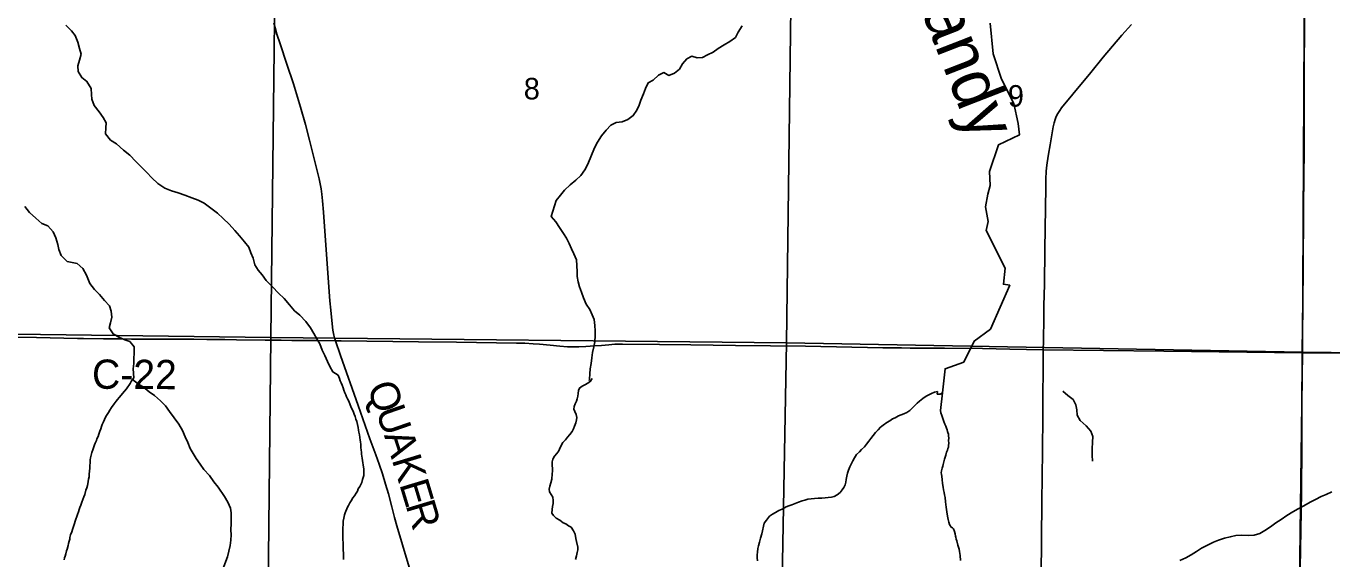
# Model space of a CAD drawing. Extents: x 0 to 34, y 0 to 22.
# Drawn here: x 3.988 to 6.524, y 15.838 to 16.874 of the extents above; entities that cross this region are included whole.
import ezdxf

# ---------------------------------------------------------------- set-up
doc = ezdxf.new("R2010")
doc.units = 0
for name, color, linetype in [('GM_X_Corporation', 7, 'Continuous'), ('GM_X_County_Road', 7, 'Continuous'), ('GM_X_County_Road_Text', 7, 'Continuous'), ('GM_X_Minor_River', 7, 'Continuous'), ('GM_X_Minor_River_Text', 7, 'Continuous'), ('GM_X_Section_Text', 7, 'Continuous'), ('GM_X_State_Route', 7, 'Continuous'), ('GM_X_Township_Road', 7, 'Continuous')]:
    doc.layers.add(name, color=color, linetype=linetype)

msp = doc.modelspace()

# ---------------------------------------------------------------- linework, layer by layer
at = {"layer": 'GM_X_Corporation'}
for points in [[(4.475, 17.2762), (4.463, 16.2688), (3.4681, 16.2816), (3.4847, 17.2912)], [(5.4781, 17.2612), (5.4651, 16.258), (4.463, 16.2688), (4.475, 17.2762)], [(6.4721, 17.2442), (6.4674, 16.2404), (5.4651, 16.258), (5.4781, 17.2612)], [(7.4742, 17.2327), (7.4675, 16.2282), (6.4674, 16.2404), (6.4721, 17.2442)], [(3.4681, 16.2816), (4.463, 16.2688), (4.4514, 15.172), (3.4532, 15.1884), (3.4534, 15.28)], [(4.463, 16.2688), (5.4651, 16.258), (5.4447, 15.1591), (4.4514, 15.172)], [(5.4651, 16.258), (6.4674, 16.2404), (6.4527, 15.1394), (5.4447, 15.1591)], [(6.4674, 16.2404), (7.4675, 16.2282), (7.4535, 15.1233), (6.4527, 15.1394)]]:
    msp.add_lwpolyline(points, close=True, dxfattribs=at)
at = {"layer": 'GM_X_County_Road'}
for points in [[(4.5885, 16.2621), (4.5867, 16.2677), (4.5855, 16.2731), (4.5838, 16.2828), (4.5822, 16.2951), (4.5795, 16.3217), (4.578, 16.3396), (4.5714, 16.4301), (4.5656, 16.5119), (4.5637, 16.5342), (4.5623, 16.5472), (4.5607, 16.5577), (4.559, 16.5669), (4.5569, 16.5767), (4.5382, 16.6521), (4.5303, 16.6825), (4.5205, 16.7162), (4.5073, 16.7613), (4.4945, 16.7999), (4.4811, 16.8393), (4.4749, 16.8582), (4.4714, 16.8701), (4.469, 16.8803)], [(3.9668, 16.2691), (4.0078, 16.2685), (4.0873, 16.2667), (4.0992, 16.2666), (4.1383, 16.266), (4.1705, 16.2658), (4.1923, 16.2655), (4.219, 16.2653), (4.2655, 16.2653), (4.2804, 16.2652), (4.3134, 16.2651), (4.3388, 16.2649), (4.3612, 16.2648), (4.3736, 16.2647), (4.3966, 16.2644), (4.4519, 16.2637), (4.4619, 16.2637), (4.483, 16.2634), (4.5041, 16.2631), (4.532, 16.2628), (4.5542, 16.2626), (4.5885, 16.2621), (4.6, 16.262), (4.7497, 16.2602), (4.8237, 16.2594), (4.9404, 16.2579), (4.9566, 16.2574), (4.9727, 16.2566), (4.985, 16.2555), (5.006, 16.2534), (5.0246, 16.2516), (5.0395, 16.2507), (5.0519, 16.2503), (5.0613, 16.2504), (5.075, 16.2509), (5.0917, 16.2521), (5.1053, 16.2533), (5.1195, 16.2546), (5.1312, 16.2555), (5.1387, 16.2558), (5.1461, 16.2559), (5.2181, 16.2549), (5.279, 16.2542), (5.366, 16.2531), (5.502, 16.2515), (5.6517, 16.2488), (5.6883, 16.2484), (5.7051, 16.2482), (5.7715, 16.2476), (5.8459, 16.2471), (5.8986, 16.2457), (5.9637, 16.2448)], [(4.7453, 15.7773), (4.7186, 15.8659), (4.7078, 15.9029), (4.7035, 15.9191), (4.6983, 15.9396), (4.6915, 15.9648), (4.686, 15.9839), (4.6799, 16.0035), (4.6735, 16.0223), (4.667, 16.0405), (4.6557, 16.0714), (4.6326, 16.1364), (4.5985, 16.2337), (4.5885, 16.2621)], [(5.9637, 16.2448), (6.198, 16.2422), (6.4665, 16.239), (6.7005, 16.2366), (6.9049, 16.2341), (7.1297, 16.2306), (7.2895, 16.2286), (7.3138, 16.2288)]]:
    msp.add_lwpolyline(points, dxfattribs=at)
at = {"layer": 'GM_X_Minor_River'}
for points in [[(4.065, 16.8753), (4.0758, 16.8648), (4.0829, 16.8552), (4.0879, 16.8422), (4.0915, 16.8304), (4.0944, 16.8194), (4.0915, 16.8073), (4.0879, 16.7964), (4.0888, 16.7857), (4.0958, 16.7738), (4.1059, 16.7661), (4.114, 16.7526), (4.1145, 16.7409), (4.1151, 16.7314), (4.1202, 16.7192), (4.1298, 16.7069), (4.1376, 16.6961), (4.1431, 16.6858), (4.1426, 16.6759), (4.142, 16.6642), (4.152, 16.6518), (4.1632, 16.6448), (4.1767, 16.6328), (4.1894, 16.6231), (4.2009, 16.6104), (4.2121, 16.5995), (4.2225, 16.5891), (4.2322, 16.5791), (4.2438, 16.5679), (4.2569, 16.5589), (4.2701, 16.5537), (4.2833, 16.5497), (4.2961, 16.5453), (4.3097, 16.5401), (4.3221, 16.5353), (4.3338, 16.5294), (4.3469, 16.5201), (4.3596, 16.51), (4.3708, 16.4999), (4.3823, 16.4887), (4.3931, 16.4764), (4.402, 16.4664), (4.4121, 16.4548), (4.4202, 16.4444), (4.4246, 16.4333), (4.4286, 16.423), (4.4321, 16.4101), (4.4384, 16.3997), (4.4462, 16.3901), (4.4543, 16.3793), (4.4662, 16.3673), (4.4781, 16.3546), (4.4889, 16.3442), (4.4994, 16.3322), (4.5094, 16.3207), (4.5195, 16.3117), (4.531, 16.2994), (4.5403, 16.2871), (4.5469, 16.2764), (4.5528, 16.266), (4.5583, 16.256), (4.563, 16.2442), (4.5681, 16.2335), (4.5732, 16.222), (4.578, 16.2121), (4.5835, 16.2017), (4.5942, 16.1957)], [(5.379, 16.8739), (5.3708, 16.8616), (5.3657, 16.8514), (5.3549, 16.8437), (5.3438, 16.8374), (5.3323, 16.8301), (5.3223, 16.8231), (5.3116, 16.8176), (5.3016, 16.8124), (5.2914, 16.8123), (5.2812, 16.8151), (5.2712, 16.81), (5.2627, 16.8003), (5.2568, 16.7901), (5.2472, 16.782), (5.2361, 16.778), (5.2263, 16.7835), (5.2164, 16.7784), (5.2056, 16.7684), (5.196, 16.7636), (5.1912, 16.7527), (5.1869, 16.7418), (5.1821, 16.7297), (5.1785, 16.7199), (5.1741, 16.7102), (5.1671, 16.6997), (5.1567, 16.6919), (5.1453, 16.6876), (5.1339, 16.6863), (5.1235, 16.6812), (5.1146, 16.6715), (5.1057, 16.6606), (5.0975, 16.6483), (5.092, 16.637), (5.0789, 16.6054), (5.0733, 16.5941), (5.0656, 16.5833), (5.0555, 16.5744), (5.0444, 16.5651), (5.0335, 16.5547), (5.0258, 16.545), (5.0172, 16.5349), (5.014, 16.5247), (5.0108, 16.5138), (5.0076, 16.5036), (5.0168, 16.4932), (5.0242, 16.4824), (5.0316, 16.4709), (5.0375, 16.4613), (5.0426, 16.451), (5.047, 16.4407), (5.0518, 16.4311), (5.0569, 16.4196), (5.0578, 16.4083), (5.0583, 16.3965), (5.0585, 16.387), (5.0602, 16.3767), (5.0627, 16.3668), (5.0663, 16.3565), (5.0707, 16.3455), (5.0758, 16.3332), (5.0828, 16.3229), (5.0875, 16.3129), (5.0911, 16.3034), (5.0928, 16.292), (5.093, 16.2817), (5.0932, 16.2722), (5.0926, 16.2605), (5.0906, 16.2507), (5.0881, 16.2393), (5.0867, 16.2291), (5.0854, 16.2182), (5.0837, 16.2079), (5.0831, 16.1977), (5.0822, 16.1879), (5.0818, 16.1849)], [(5.7677, 16.1608), (5.773, 16.208), (5.8091, 16.2204), (5.8295, 16.2615), (5.8614, 16.2851), (5.8985, 16.3701), (5.8861, 16.3721), (5.8898, 16.4036), (5.853, 16.4765), (5.8566, 16.4942), (5.8512, 16.5222), (5.8562, 16.5471), (5.8606, 16.5637), (5.8589, 16.5912), (5.8766, 16.6427), (5.9175, 16.6625), (5.9149, 16.6847), (5.9067, 16.7234), (5.8826, 16.7707), (5.8662, 16.8197), (5.8603, 16.8793)], [(3.9853, 16.5234), (3.9942, 16.5114), (4.0065, 16.5002), (4.0181, 16.4901), (4.0298, 16.4854), (4.0402, 16.4742), (4.0453, 16.4623), (4.0492, 16.4494), (4.0513, 16.4395), (4.056, 16.428), (4.0672, 16.4164), (4.077, 16.4144), (4.0872, 16.4123), (4.0977, 16.4026), (4.105, 16.3896), (4.1116, 16.3735), (4.1208, 16.3616), (4.1305, 16.352), (4.1402, 16.3404)], [(4.1402, 16.3404), (4.1495, 16.3304), (4.1527, 16.3201), (4.154, 16.3083), (4.1519, 16.2973), (4.1494, 16.2871), (4.1568, 16.2756), (4.1681, 16.269), (4.1794, 16.2642), (4.1892, 16.261), (4.1977, 16.2502), (4.1975, 16.2381), (4.1969, 16.2279), (4.1967, 16.218), (4.1958, 16.2078)], [(4.1101, 15.9981), (4.1105, 16.0015), (4.1108, 16.0099), (4.1113, 16.0137), (4.1114, 16.0197), (4.112, 16.0254), (4.1121, 16.0307), (4.113, 16.0349), (4.1143, 16.0402), (4.1156, 16.0451), (4.1176, 16.0503), (4.1189, 16.0545), (4.1209, 16.0598), (4.1222, 16.0631), (4.1242, 16.0684), (4.1254, 16.0718), (4.1275, 16.0763), (4.1287, 16.0808), (4.1308, 16.0865), (4.1328, 16.0913), (4.1341, 16.0959), (4.1357, 16.0996), (4.1378, 16.1049), (4.1402, 16.1094), (4.1426, 16.1154), (4.1454, 16.1187), (4.1478, 16.1232), (4.1506, 16.1277), (4.1533, 16.1326), (4.1589, 16.14), (4.1624, 16.1448), (4.1652, 16.1482), (4.1683, 16.1519), (4.1722, 16.1563), (4.175, 16.1601), (4.1789, 16.1645), (4.1825, 16.169), (4.1896, 16.179), (4.192, 16.1828), (4.1944, 16.1869), (4.1967, 16.1902), (4.1958, 16.2078)], [(4.1944, 16.1869), (4.2061, 16.1781), (4.2158, 16.1722), (4.2266, 16.1631), (4.237, 16.1556), (4.2488, 16.1458), (4.2588, 16.136), (4.2665, 16.1251), (4.2756, 16.1127), (4.2844, 16.1003), (4.2916, 16.088), (4.297, 16.0757), (4.3016, 16.0649), (4.3066, 16.053), (4.312, 16.043), (4.3182, 16.0333), (4.3258, 16.0224), (4.3328, 16.012), (4.3438, 16.0007), (4.3522, 15.9883), (4.3606, 15.9778), (4.3734, 15.9596), (4.3799, 15.9488), (4.3849, 15.9372), (4.3858, 15.9277), (4.3863, 15.917), (4.3864, 15.9072), (4.3857, 15.895), (4.3861, 15.8851), (4.3855, 15.8749), (4.384, 15.8643), (4.3818, 15.8534), (4.3789, 15.8424), (4.3699, 15.8184)], [(4.5942, 16.1957), (4.5962, 16.1888)], [(4.5962, 16.1888), (4.5976, 16.1846), (4.5998, 16.1804), (4.6019, 16.1761), (4.6037, 16.1711), (4.6051, 16.1665), (4.6072, 16.1612), (4.609, 16.1573), (4.6104, 16.1535), (4.6122, 16.1492), (4.6147, 16.1446), (4.6172, 16.1381), (4.62, 16.1312), (4.6229, 16.1254), (4.625, 16.1196), (4.6268, 16.115), (4.6285, 16.11), (4.6299, 16.1054), (4.6313, 16.0993), (4.6326, 16.0936), (4.6336, 16.0886), (4.6342, 16.0844), (4.6352, 16.0794), (4.6359, 16.0741), (4.6369, 16.0691), (4.6371, 16.0657), (4.6377, 16.0604), (4.638, 16.055), (4.6386, 16.0497), (4.6392, 16.0459), (4.6395, 16.0417), (4.6398, 16.0383), (4.6404, 16.0344), (4.641, 16.0295), (4.6417, 16.0253), (4.6427, 16.0211), (4.6433, 16.0169), (4.644, 16.0131), (4.6436, 16.0005), (4.6428, 15.9968), (4.6411, 15.993), (4.6398, 15.987), (4.6378, 15.9832), (4.6362, 15.9791), (4.633, 15.9746), (4.6314, 15.9701), (4.629, 15.966), (4.6254, 15.9608), (4.6227, 15.957), (4.6191, 15.9514), (4.6163, 15.9473), (4.6139, 15.9425), (4.6123, 15.9391), (4.6074, 15.9278), (4.6062, 15.9241), (4.6049, 15.9177), (4.6039, 15.9116), (4.6037, 15.9055), (4.6032, 15.8991), (4.603, 15.8938), (4.6029, 15.89), (4.6028, 15.8854), (4.603, 15.8793), (4.6033, 15.8755), (4.6035, 15.8706), (4.6037, 15.8652), (4.6035, 15.8561), (4.604, 15.8489), (4.6042, 15.8428), (4.6045, 15.8371)], [(5.0876, 16.189), (5.0841, 16.1837), (5.079, 16.1797), (5.0732, 16.1768), (5.0679, 16.1743), (5.0628, 16.1703), (5.0608, 16.1654), (5.0599, 16.1601), (5.0593, 16.1548), (5.0584, 16.1495), (5.0568, 16.1446), (5.054, 16.1398), (5.0523, 16.1345), (5.0518, 16.1296), (5.0535, 16.1246), (5.056, 16.1188), (5.0574, 16.1134), (5.0569, 16.1085), (5.0556, 16.1029), (5.0531, 16.0965), (5.0511, 16.0912), (5.0487, 16.086), (5.0439, 16.0804), (5.0396, 16.0752), (5.0353, 16.0696), (5.0302, 16.0644), (5.0254, 16.0547), (5.0229, 16.0483), (5.019, 16.0431), (5.0143, 16.0383), (5.0107, 16.0323), (5.0094, 16.027), (5.0096, 16.0202), (5.0106, 16.0141), (5.01, 16.0088), (5.0099, 16.0038), (5.0088, 15.9932), (5.0071, 15.9861), (5.005, 15.98), (5.0037, 15.974), (5.0044, 15.969), (5.0076, 15.9636), (5.0109, 15.9586), (5.0115, 15.9517), (5.0113, 15.946), (5.0104, 15.94), (5.0095, 15.9347), (5.0092, 15.9275), (5.0121, 15.9225), (5.0177, 15.9174), (5.0244, 15.9134), (5.0307, 15.9086), (5.036, 15.9066), (5.0412, 15.9026), (5.0464, 15.8998), (5.0511, 15.8929), (5.054, 15.8863), (5.0553, 15.8783), (5.057, 15.8722), (5.0597, 15.8614), (5.0592, 15.8561), (5.0583, 15.8508), (5.057, 15.8444), (5.0549, 15.8373)], [(5.7524, 16.1622), (5.7463, 16.1597), (5.7413, 16.1572), (5.7359, 16.1543), (5.7297, 16.1503), (5.7235, 16.1451), (5.7184, 16.1411), (5.7044, 16.1267), (5.6985, 16.1226), (5.6928, 16.1205), (5.6878, 16.1184), (5.6824, 16.1163), (5.6759, 16.1127), (5.6709, 16.1105), (5.6658, 16.1069), (5.6597, 16.1032), (5.6527, 16.0985), (5.6477, 16.0944), (5.6426, 16.0893), (5.6375, 16.0837), (5.6332, 16.0785), (5.6288, 16.0726), (5.6249, 16.067), (5.6202, 16.0614), (5.6162, 16.0562), (5.6108, 16.051), (5.6065, 16.0462), (5.601, 16.0411), (5.597, 16.0351), (5.5938, 16.0291), (5.5906, 16.0227), (5.5878, 16.0171), (5.5853, 16.0111), (5.5833, 16.0051), (5.582, 15.9994), (5.5807, 15.993), (5.5801, 15.9877), (5.5788, 15.9824), (5.576, 15.9772), (5.5732, 15.9723), (5.5689, 15.9675), (5.5635, 15.9631), (5.5577, 15.9598), (5.5524, 15.9584), (5.5455, 15.9575), (5.5398, 15.9569), (5.5333, 15.9567), (5.5261, 15.9565), (5.5193, 15.9556), (5.5128, 15.9554), (5.5063, 15.9544), (5.5006, 15.9527), (5.4952, 15.9513), (5.4883, 15.9485), (5.4818, 15.946), (5.4749, 15.9435), (5.4695, 15.9414), (5.4642, 15.9397), (5.4565, 15.9353), (5.4499, 15.9325), (5.4434, 15.9285), (5.4376, 15.9252), (5.4318, 15.9212), (5.4259, 15.9134), (5.4212, 15.9078), (5.4199, 15.9022), (5.4181, 15.8927), (5.4168, 15.887), (5.4143, 15.8788), (5.4121, 15.8712), (5.4104, 15.864), (5.4091, 15.8584), (5.4082, 15.8512), (5.4076, 15.8463), (5.4078, 15.8402), (5.4084, 15.8345)], [(5.7677, 16.1608), (5.7633, 16.1588), (5.7576, 16.1586), (5.7581, 16.1635), (5.7524, 16.1622)], [(5.7638, 16.1269), (5.7677, 16.1608)], [(6.0014, 16.1646), (6.0114, 16.1556), (6.0218, 16.1481), (6.0272, 16.1377), (6.0288, 16.1278), (6.0293, 16.1179), (6.035, 16.1071), (6.0469, 16.0969), (6.0561, 16.0867), (6.06, 16.076), (6.0593, 16.0654), (6.0589, 16.0521), (6.0589, 16.0399), (6.0594, 16.0281)], [(5.8029, 15.835), (5.8025, 15.8449), (5.8018, 15.8487), (5.8008, 15.8529), (5.8002, 15.8571), (5.7988, 15.8613), (5.7974, 15.8652), (5.7954, 15.8736), (5.7944, 15.877), (5.7937, 15.8805), (5.793, 15.8828), (5.7924, 15.8873), (5.791, 15.8919), (5.7893, 15.8966), (5.7871, 15.8989), (5.7841, 15.9005), (5.7827, 15.9036), (5.7816, 15.9055), (5.7802, 15.9098), (5.7792, 15.9147), (5.7779, 15.9216), (5.7763, 15.9296), (5.775, 15.9392), (5.7738, 15.9491), (5.773, 15.9575), (5.772, 15.9628), (5.771, 15.9674), (5.77, 15.9724), (5.769, 15.9781), (5.7681, 15.985), (5.7672, 15.9926), (5.7666, 15.9987), (5.766, 16.0033), (5.7653, 16.0055), (5.7662, 16.0097), (5.7675, 16.015), (5.7688, 16.0187), (5.7693, 16.0221), (5.7718, 16.0323), (5.7731, 16.0361), (5.7744, 16.0402), (5.7757, 16.0455), (5.7777, 16.05), (5.7785, 16.053), (5.7794, 16.0556), (5.7798, 16.0587), (5.78, 16.0636), (5.7798, 16.0685), (5.7799, 16.0731), (5.7797, 16.0773), (5.7794, 16.0811), (5.7784, 16.0842), (5.7777, 16.0861), (5.777, 16.0891), (5.7756, 16.0922), (5.7742, 16.0961), (5.7724, 16.0999), (5.7703, 16.1053), (5.7686, 16.1111), (5.7665, 16.1172), (5.7647, 16.1222), (5.7638, 16.1269)], [(4.0615, 15.8365), (4.0623, 15.8406), (4.0636, 15.844), (4.0648, 15.8482), (4.0661, 15.8538), (4.0678, 15.8576), (4.0695, 15.8644), (4.0703, 15.8685), (4.0716, 15.8727), (4.0725, 15.8768), (4.073, 15.8802), (4.0742, 15.8855), (4.0763, 15.8908), (4.0776, 15.8957), (4.0792, 15.8994), (4.0804, 15.9032), (4.0817, 15.9073), (4.0833, 15.9115), (4.0846, 15.9156), (4.0862, 15.9205), (4.0875, 15.925), (4.0892, 15.9299), (4.0908, 15.9344), (4.0921, 15.9386), (4.0941, 15.9431), (4.0961, 15.9484), (4.0978, 15.9536), (4.0999, 15.9593), (4.1015, 15.9634), (4.104, 15.9717), (4.1057, 15.9766), (4.1069, 15.9811), (4.1074, 15.9845), (4.1083, 15.9887), (4.1092, 15.9936), (4.1101, 15.9981)], [(6.5244, 15.9687), (6.5132, 15.9633), (6.5032, 15.9594), (6.4924, 15.9536), (6.4824, 15.9489), (6.4697, 15.9413), (6.4589, 15.9355), (6.4485, 15.9298), (6.4366, 15.9229), (6.4257, 15.9148), (6.4156, 15.9083), (6.4052, 15.901), (6.394, 15.8937), (6.384, 15.8879), (6.3736, 15.8847), (6.3614, 15.8836), (6.3493, 15.8843), (6.3379, 15.8839), (6.3269, 15.8811), (6.3154, 15.8784), (6.3043, 15.8745), (6.2943, 15.871), (6.2824, 15.8653), (6.2712, 15.8595), (6.2612, 15.853), (6.2511, 15.846), (6.2403, 15.8402), (6.2292, 15.8356)]]:
    msp.add_lwpolyline(points, dxfattribs=at)
at = {"layer": 'GM_X_State_Route'}
msp.add_lwpolyline([(5.9595, 15.8049), (5.9609, 15.949), (5.9622, 16.0478), (5.9627, 16.1167), (5.9637, 16.2448), (5.964, 16.2617), (5.9647, 16.3078), (5.965, 16.3307), (5.9657, 16.3716), (5.9667, 16.4399), (5.9684, 16.5609), (5.9686, 16.5771), (5.9693, 16.5914), (5.97, 16.5982), (5.9712, 16.6081), (5.9738, 16.6246), (5.9769, 16.6429), (5.9802, 16.6625), (5.9829, 16.6778), (5.9847, 16.6858), (5.9867, 16.6923), (5.989, 16.6981), (5.9919, 16.7037), (5.9955, 16.7094), (5.9993, 16.7146), (6.021, 16.7411), (6.0563, 16.7836), (6.0802, 16.813), (6.1161, 16.8559), (6.1347, 16.8768)], dxfattribs=at)
at = {"layer": 'GM_X_Township_Road'}
for points in [[(6.4665, 16.239), (6.4682, 16.3954), (6.4693, 16.5245), (6.4702, 16.6338), (6.4702, 16.6971), (6.4703, 16.7437), (6.4708, 16.9189), (6.4715, 17.0226), (6.4713, 17.0714)], [(6.4624, 15.8204), (6.4655, 15.9682), (6.4659, 16.0588), (6.4662, 16.1265), (6.4665, 16.239)]]:
    msp.add_lwpolyline(points, dxfattribs=at)

# ---------------------------------------------------------------- texts
at = {"layer": 'GM_X_County_Road_Text'}
for s, height, rotation, p in [('C-22', 0.05682, 359.6571, (4.1156, 16.1691)), ('Q', 0.0568, 289.8451, (4.6493, 16.1725)), ('U', 0.0568, 289.1532, (4.6663, 16.1257)), ('A', 0.0568, 287.8584, (4.6826, 16.0787)), ('K', 0.0568, 286.8831, (4.6978, 16.0314)), ('E', 0.0568, 286.7969, (4.7123, 15.9836)), ('R', 0.0568, 286.799, (4.7246, 15.9429))]:
    msp.add_text(s, height=height, rotation=rotation, dxfattribs=at).set_placement(p)
at = {"layer": 'GM_X_Minor_River_Text'}
msp.add_text('Sandy', height=0.09467, rotation=291.2218, dxfattribs=at).set_placement((5.6966, 16.9805))
at = {"layer": 'GM_X_Section_Text'}
for s, p in [('8', (4.9545, 16.7312)), ('9', (5.8949, 16.7171))]:
    msp.add_text(s, height=0.0419, rotation=0, dxfattribs=at).set_placement(p)

doc.saveas('drawing.dxf')
